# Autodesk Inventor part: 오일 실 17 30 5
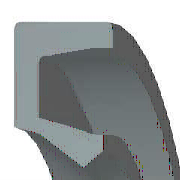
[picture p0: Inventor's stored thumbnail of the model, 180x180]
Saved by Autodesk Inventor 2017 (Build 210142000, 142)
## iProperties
IsCustomPart: 1
Created: 2012-02
Part Number: 오일 실 17 30 5
Material: 고무
Description: 오일 실 - 비스프링, 금속 케이스 GM
Document SubType Name: Modeling
Standard: JIS B 2402
Designer: mduedu
Standards Organization: JIS
Language: ko-KR
Size Designation: 17 30 5 B
Categories: <MemberInstance><Categories><Category DisplayName="샤프트 부품" InternalName="7f7aeb1f-a693-4053-b835-cee3144e0d98" Mnemonic="SHFT"><Category DisplayName="실링" Intern
Density: 0.93 g/cm^3
Appearance: Rubber-Black
Author: mduedu
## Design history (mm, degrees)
body "Solid1"
revolve "회전1" stored, may be unused: angle "d27" = 360 deg
fillet "모깎기1" dims "d28" = 0.25 (= 0.05 x b)
chamfer "모따기1" distance "d29" = 0.07143 (= 0.0142857 x b); stored, may be unused: second distance "d30" = 0.25 (= 0.05 x b), angle "d35" = 45 deg
sketch "스케치2"
  geometry: L1 (-9.367, -3.238)-(-10.233, -3.863); L2 (-8.5, -1.625)-(-9.367, -3.238); L3 (-9.15, -1)-(-8.5, -1.625); L4 (-11.317, -3.75)-(-9.15, -1); L5 (-13.075, -3.75)-(-11.317, -3.75); L6 (-14.375, -1.25)-(-13.075, -3.75); L7 (-14.375, 0)-(-14.375, -1.25); L8 (-15, 0)-(-14.375, 0); L9 (-15, -5)-(-15, 0); L10 (-11.129, -5)-(-15, -5); L11 (-10.233, -3.863)-(-11.129, -5); L12 (0, -9.6)-(0, 1.6) reference; L13 (-14, 0)-(-28, 0) reference
  constraints: 22 end point, 3 horizontal, 2 vertical, 1 parallel
  dimensions: "d2" = 5 distance of L9.start L8.start (= b); "d4" = 1 vertical distance of L8.start L3.start (= 0.2 x b); "d6" = 0.625 distance of L8.start L7.start (= 0.125 x b); "d8" = 1.25 distance of L7.start L6.start (= 0.25 x b); "d10" = 1.25 vertical distance of L5.start L9.start (= 0.25 x b); "d12" = 1.3 horizontal distance of L6.start L5.start (= 0.1 x dd - 0.1 x Diam); "d14" = 1.6129 vertical distance of L2.start L1.start (= 0.322581 x b); "d16" = 0.86667 horizontal distance of L1.start L1.end (= 0.0666667 x dd - 0.0666667 x Diam); "d18" = 0.86667 horizontal distance of L2.start L1.start (= 0.0666667 x dd - 0.0666667 x Diam); "d20" = 0.625 vertical distance of L3.start L2.start (= 0.125 x b); "d22" = 0.65 horizontal distance of L3.start L2.start (= 0.05 x dd - 0.05 x Diam); "d24" = 0.625 vertical distance of L1.start L1.end (= 0.125 x b); "d26" = 2.16667 horizontal distance of L4.start L3.start (= 0.166667 x dd - 0.166667 x Diam); "d31" = 0 distance between parallel lines of L8 L13; "d32" = 15 distance between parallel lines of L12 L9 (= 0.5 x dd); "d33" = 8.5 distance from line of L12 L2.start (= 0.5 x Diam)
other parameters: "Diam" = 17 [user parameter; used in 6 equation terms], "b" = 5 [user parameter; used in 11 equation terms], "d1" = 8 (derived), "d3" = 1.6 (derived), "d5" = 1 (derived), "d7" = 2 (derived), "d9" = 2 (derived), "d11" = 2 (derived), "d13" = 2.58065 (derived), "d15" = 1.33333 (derived), "d17" = 1.33333 (derived), "d19" = 1 (derived), "d21" = 1 (derived), "d23" = 1 (derived), "d25" = 3.33333 (derived), "d34" = 0
